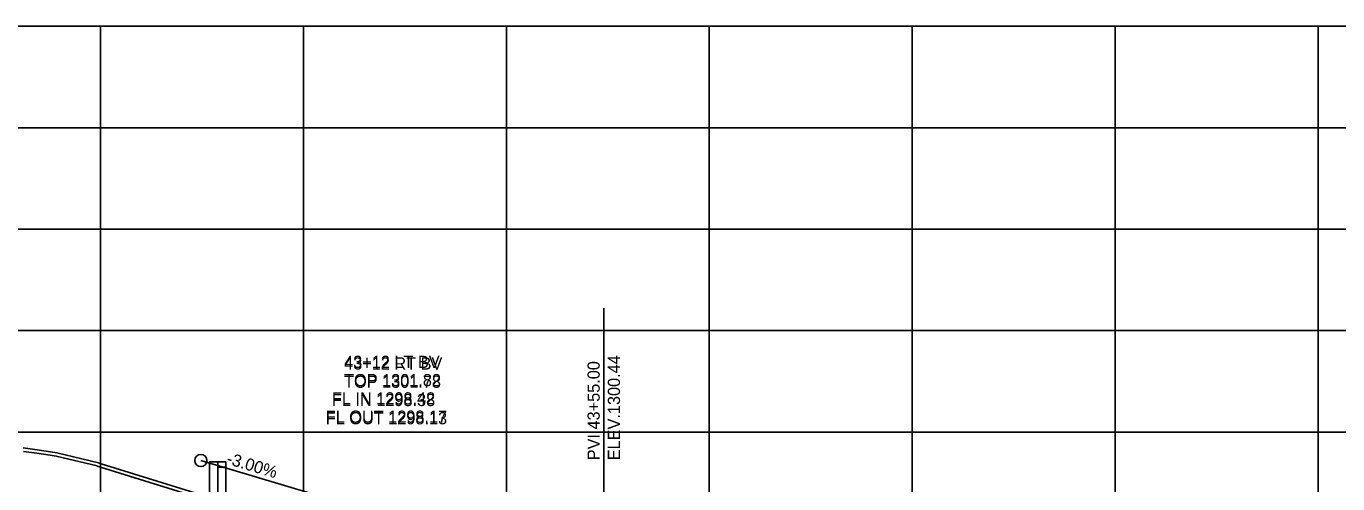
# Model space of a CAD drawing. Extents: x 670877 to 686811, y 705985 to 708501.
# Drawn here: x 685636 to 686283, y 707463 to 707688 of the extents above; entities that cross this region are included whole.
import ezdxf

# ---------------------------------------------------------------- set-up
doc = ezdxf.new("R2010")
doc.units = 0
for name, color, linetype in [('37', 7, 'Continuous'), ('DRAINAGE_HGL LEFT', 7, 'Continuous'), ('Profile Drainage Annot Left', 7, 'Continuous'), ('Profile Drainage Annot Right', 7, 'Continuous'), ('R_Drainage Extensions_RIGHT', 7, 'Continuous'), ('R_Drainage LEFT', 7, 'Continuous'), ('R_Drainage RIGHT', 7, 'Continuous'), ('R_Exist Surface', 7, 'Continuous'), ('R_Vert Alg', 7, 'Continuous'), ('R_Vert Alg Annot', 7, 'Continuous')]:
    doc.layers.add(name, color=color, linetype=linetype)

msp = doc.modelspace()

# ---------------------------------------------------------------- linework, layer by layer
at = {"layer": '37'}
for p, q in [((684473.03, 707688.43), (686573.03, 707688.43)), ((685673.03, 707038.43), (685673.03, 707688.43)), ((685773.03, 707038.43), (685773.03, 707688.43)), ((685873.03, 707038.43), (685873.03, 707688.43)), ((685973.03, 707038.43), (685973.03, 707688.43)), ((686073.03, 707038.43), (686073.03, 707688.43)), ((686173.03, 707038.43), (686173.03, 707688.43)), ((686273.03, 707038.43), (686273.03, 707688.43)), ((684473.03, 707638.43), (686573.03, 707638.43)), ((684473.03, 707588.43), (686573.03, 707588.43)), ((684473.03, 707538.43), (686573.03, 707538.43)), ((684473.03, 707488.43), (686573.03, 707488.43))]:
    msp.add_line(p, q, dxfattribs=at)
at = {"layer": 'DRAINAGE_HGL LEFT'}
msp.add_lwpolyline([(685634.93, 707480.62), (685641.88, 707479.61), (685648.45, 707478.64), (685651.62, 707478.19), (685672.04, 707473.29), (685672.31, 707473.12), (685672.47, 707473.04), (685673.48, 707472.79), (685740.24, 707452.02)], dxfattribs=at)
at = {"layer": 'R_Drainage Extensions_RIGHT'}
msp.add_lwpolyline([(685730.82, 707473.73), (685726.82, 707473.73), (685726.82, 707458.73), (685730.82, 707457.06), (685730.82, 707473.73)], dxfattribs=at)
at = {"layer": 'R_Drainage LEFT'}
for points in [[(685730.9, 707437.13), (685730.9, 707471.13)], [(685730.9, 707471.13), (685734.9, 707471.13)], [(685734.9, 707471.13), (685734.9, 707452.07)]]:
    msp.add_lwpolyline(points, dxfattribs=at)
at = {"layer": 'R_Drainage RIGHT'}
for points in [[(685730.82, 707437.23), (685730.82, 707473.73)], [(685730.82, 707473.73), (685734.83, 707473.73)], [(685734.83, 707473.73), (685734.83, 707452.23)]]:
    msp.add_lwpolyline(points, dxfattribs=at)
at = {"layer": 'R_Exist Surface'}
msp.add_lwpolyline([(685635.1, 707478.91), (685641.64, 707477.96), (685648.21, 707476.99), (685651.31, 707476.55), (685671.38, 707471.73), (685671.47, 707471.67), (685671.87, 707471.46), (685673.04, 707471.18), (685739.71, 707450.44)], dxfattribs=at)
at = {"layer": 'R_Vert Alg'}
msp.add_line((685722.55, 707474.43), (685778.03, 707457.81), dxfattribs=at)
msp.add_circle((685722.55, 707474.43), 3, dxfattribs=at)
at = {"layer": 'R_Vert Alg Annot'}
msp.add_line((685921.03, 707442.83), (685921.03, 707549.53), dxfattribs=at)

# ---------------------------------------------------------------- texts
at = {"layer": 'Profile Drainage Annot Left'}
for s, p in [('43+12 LT BV', (685793.12, 707520.03)), ('TOP 1301.82', (685793.09, 707511.03)), ('FL IN 1298.42', (685787.09, 707502.03)), ('FL OUT 1298.17', (685784.08, 707493.03))]:
    msp.add_text(s, height=6, dxfattribs=at).set_placement(p)
at = {"layer": 'Profile Drainage Annot Right'}
for s, p in [('43+12 RT BV', (685793.12, 707519.23)), ('TOP 1301.78', (685793.1, 707510.23)), ('FL IN 1298.38', (685787.1, 707501.23)), ('FL OUT 1298.13', (685784.09, 707492.23))]:
    msp.add_text(s, height=6, dxfattribs=at).set_placement(p)
at = {"layer": 'R_Vert Alg Annot'}
for s, rotation, p in [('PVI 43+55.00', 90, (685919.03, 707474.53)), ('ELEV.1300.44', 90, (685929.03, 707474.53)), ('-3.00%', 343.32278, (685734.77, 707472.86))]:
    msp.add_text(s, height=6, rotation=rotation, dxfattribs=at).set_placement(p)

doc.saveas('drawing.dxf')
